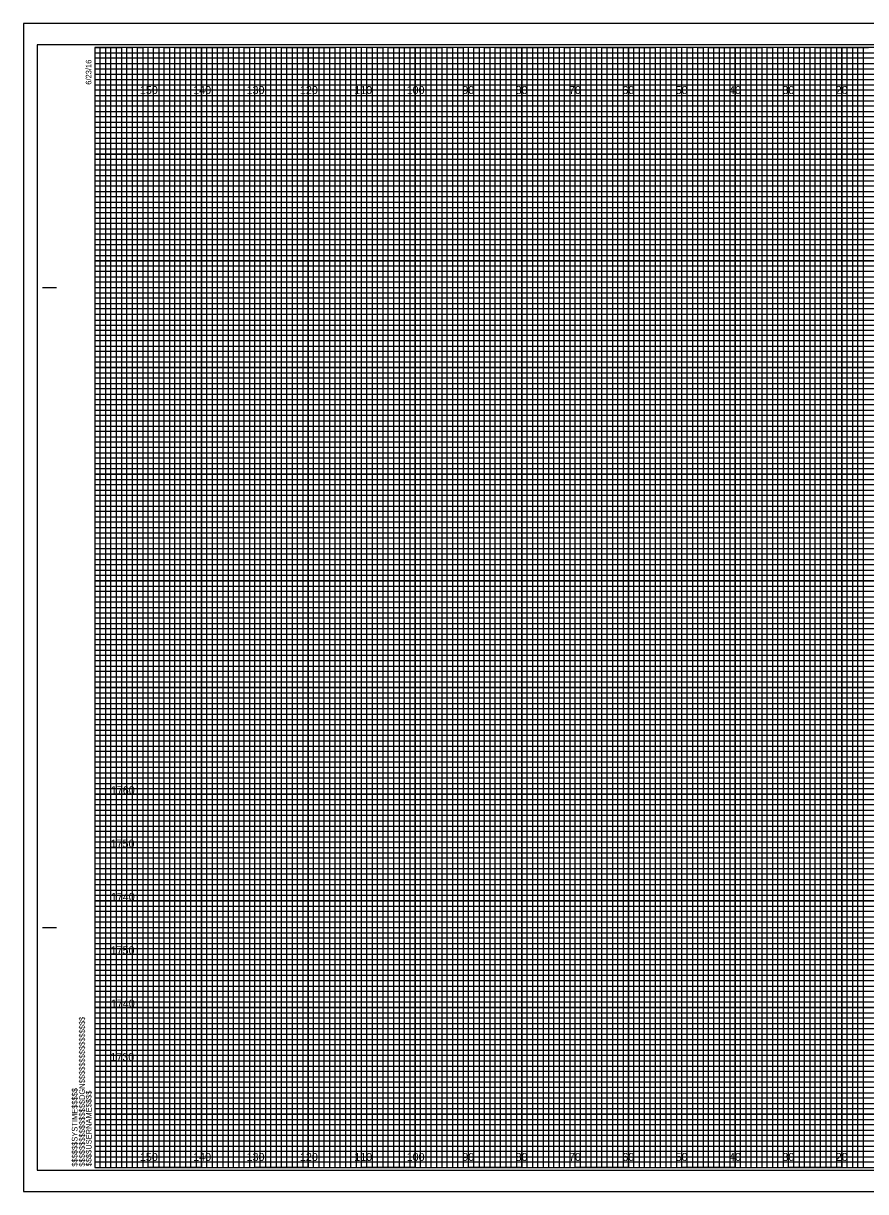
# Model space of a CAD drawing. Extents: x -13 to 323, y -5 to 434.
# Drawn here: x -13.4 to 144.5, y 215.5 to 434.5 of the extents above; entities that cross this region are included whole.
import ezdxf

# ---------------------------------------------------------------- set-up
doc = ezdxf.new("R2010")
doc.units = 0
for name, color, linetype in [('Raster_Level_0', 7, 'Continuous'), ('Scratch_Level_3', 7, 'Continuous'), ('Sheet Cross Section CELL', 7, 'Continuous'), ('Sheet Cross Section Grid Major CELL', 7, 'Continuous'), ('Sheet Cross Section Grid Middle CELL', 7, 'Continuous'), ('Sheet Cross Section Grid Minor 1 CELL', 7, 'Continuous'), ('Sheet Cross Section Grid Minor 2 CELL', 7, 'Continuous'), ('Sheet Cutting Line CELL', 7, 'Continuous'), ('Sheet DOT Grid CELL', 7, 'Continuous'), ('Sheet Plot Border Inside CELL', 7, 'Continuous'), ('Sheet Plot Border Outside CELL', 7, 'Continuous')]:
    doc.layers.add(name, color=color, linetype=linetype)

msp = doc.modelspace()

# ---------------------------------------------------------------- linework, layer by layer
at = {"layer": 'Sheet Cross Section CELL'}
for p, q in [((-9.8, 385), (-7.3, 385)), ((-9.7, 385), (-7.2, 385)), ((-9.8, 265), (-7.3, 265)), ((-9.7, 265), (-7.2, 265)), ((0, 220), (0, 220)), ((0, 220), (0, 220)), ((0, 220), (0, 220)), ((0, 220), (0, 220)), ((0, 220), (0, 220)), ((0, 220), (0, 220)), ((0, 220), (0, 220))]:
    msp.add_line(p, q, dxfattribs=at)
msp.add_lwpolyline([(320, 430), (0, 430), (0, 220), (320, 220)], close=True, dxfattribs=at)
at = {"layer": 'Sheet Cross Section Grid Major CELL'}
for p, q in [((10, 430), (0, 430)), ((10, 220), (10, 430)), ((30, 430), (20, 430)), ((20, 430), (20, 220)), ((30, 220), (30, 430)), ((50, 430), (40, 430)), ((40, 430), (40, 220)), ((50, 220), (50, 430)), ((70, 430), (60, 430)), ((60, 430), (60, 220)), ((70, 220), (70, 430)), ((90, 430), (80, 430)), ((80, 430), (80, 220)), ((90, 220), (90, 430)), ((110, 430), (100, 430)), ((100, 430), (100, 220)), ((110, 220), (110, 430)), ((130, 430), (120, 430)), ((120, 430), (120, 220)), ((130, 220), (130, 430)), ((150, 430), (140, 430)), ((140, 430), (140, 220)), ((20, 220), (10, 220)), ((40, 220), (30, 220)), ((60, 220), (50, 220)), ((80, 220), (70, 220)), ((100, 220), (90, 220)), ((120, 220), (110, 220)), ((140, 220), (130, 220))]:
    msp.add_line(p, q, dxfattribs=at)
for points in [[(0, 420), (320, 420), (320, 410), (0, 410)], [(0, 400), (320, 400), (320, 390), (0, 390)], [(0, 380), (320, 380), (320, 370), (0, 370)], [(0, 360), (320, 360), (320, 350), (0, 350)], [(0, 340), (320, 340), (320, 330), (0, 330)], [(0, 320), (320, 320), (320, 310), (0, 310)], [(0, 300), (320, 300), (320, 290), (0, 290)], [(0, 280), (320, 280), (320, 270), (0, 270)], [(0, 260), (320, 260), (320, 250), (0, 250)], [(0, 240), (320, 240), (320, 230), (0, 230)]]:
    msp.add_lwpolyline(points, dxfattribs=at)
at = {"layer": 'Sheet Cross Section Grid Middle CELL'}
for points in [[(0, 430), (5, 430), (5, 220), (15, 220), (15, 430), (25, 430), (25, 220), (35, 220), (35, 430), (45, 430), (45, 220), (55, 220), (55, 430), (65, 430), (65, 220), (75, 220), (75, 430), (85, 430), (85, 220), (95, 220), (95, 430), (105, 430), (105, 220), (115, 220), (115, 430), (125, 430), (125, 220), (135, 220), (135, 430), (145, 430)], [(0, 425), (275, 425)], [(0, 405), (320, 405), (320, 415), (0, 415)], [(0, 385), (320, 385), (320, 395), (0, 395)], [(0, 365), (320, 365), (320, 375), (0, 375)], [(0, 345), (320, 345), (320, 355), (0, 355)], [(0, 325), (320, 325), (320, 335), (0, 335)], [(0, 305), (320, 305), (320, 315), (0, 315)], [(0, 285), (320, 285), (320, 295), (0, 295)], [(0, 265), (320, 265), (320, 275), (0, 275)], [(0, 245), (320, 245), (320, 255), (0, 255)], [(0, 225), (320, 225), (320, 235), (0, 235)]]:
    msp.add_lwpolyline(points, dxfattribs=at)
at = {"layer": 'Sheet Cross Section Grid Minor 1 CELL'}
for p, q in [((0, 429), (260, 429)), ((260, 427.98), (0, 427.98)), ((0, 427.98), (0, 427)), ((0, 427), (260, 427)), ((260, 425.89), (0, 425.89)), ((0, 425.89), (0, 424)), ((0, 424), (320, 424))]:
    msp.add_line(p, q, dxfattribs=at)
for points in [[(0, 423), (270, 423), (320, 423), (320, 422), (0, 422)], [(0, 421), (320, 421), (320, 419), (0, 419)], [(0, 418), (320, 418), (320, 417), (0, 416.98)], [(0, 416), (320, 416), (320, 414), (0, 414)], [(0, 413), (320, 413), (320, 412), (0, 412)], [(0, 411), (320, 411), (320, 409), (0, 409)], [(0, 408), (320, 408), (320, 407), (0, 407)], [(0, 406), (320, 406), (320, 404), (0, 404)], [(0, 403), (320, 403), (320, 402), (0, 402)], [(0, 401), (320, 401), (320, 399), (0, 399)], [(0, 398), (320, 398), (320, 397), (0, 397)], [(0, 396), (320, 396), (320, 393.95), (320, 393), (320, 392), (0, 392)], [(0, 394), (320, 394), (320, 393), (0, 393)], [(0, 391), (320, 391), (320, 389), (0, 389.03)], [(0, 389.03), (320, 389), (320, 388), (0, 388)], [(0, 387), (320, 387), (320, 386), (0, 386)], [(0, 384), (320, 384), (320, 383), (0, 383)], [(0, 382), (320, 382), (320, 381), (0, 381)], [(-0.07, 378.89), (320, 378.89), (320, 377.88), (-0.07, 377.88)], [(0, 377), (320, 377), (320, 376), (0, 376)], [(0, 374), (320, 374), (320, 373), (0, 373)], [(0, 372), (320, 372), (320, 371), (0, 371)], [(0, 369), (320, 369), (320, 368), (0, 368)], [(0, 367), (320, 367), (320, 366), (0, 366)], [(0, 364), (320, 364), (320, 363), (0, 363)], [(0, 362), (320, 362), (320, 361), (0, 361)], [(0, 359), (320, 359), (319.99, 357.98), (0, 358)], [(0, 357), (320, 357), (320, 356), (0, 356)], [(0, 354), (320, 354), (320, 353), (0, 353)], [(0, 352), (320, 352), (320, 351), (0, 351)], [(0, 349), (320, 349), (320, 348), (0, 348)], [(0, 347), (320, 347), (320, 346), (0, 346)], [(0, 344), (320, 344), (320, 343), (0, 343)], [(0, 342), (320, 342), (320, 341), (0, 341)], [(0, 339), (320, 339), (320, 338), (0, 338)], [(0, 336.99), (320.07, 336.91), (320, 336), (0, 336)], [(0, 334), (320, 334), (320, 333), (0, 333)], [(0, 332), (320, 332), (320, 331), (0, 331)], [(0, 329), (320, 329), (320, 328), (0, 328)], [(0, 327), (320, 327), (320, 326), (0, 326)], [(0, 324), (320, 324), (320, 323), (0, 323)], [(0, 322), (320, 322), (320, 321), (0, 321)], [(0, 319), (320, 319), (320, 318), (0, 318)], [(0, 317), (320, 317), (320, 316), (0, 316)], [(0, 314), (320, 314), (320, 313), (0, 313)], [(0, 312), (320, 312), (320, 311), (0, 311)], [(0, 309), (320, 309), (320, 308), (0, 308)], [(0, 307), (320, 307), (320, 306), (0, 306)], [(0, 304), (320, 304), (320, 303), (0, 303)], [(0, 302), (320, 302), (320, 301), (0, 301)], [(0, 299), (320, 299), (319.99, 297.98), (0, 298)], [(0, 297), (320, 297), (320, 296), (0, 296)], [(0, 294), (320, 294), (320, 293), (0, 293)], [(0, 292), (320, 292), (320, 291), (0, 291)], [(0, 289), (320, 289), (320, 288), (0, 288)], [(0, 287), (320, 287), (320, 286), (0, 286)], [(0, 284), (320, 284), (320, 283), (0, 283)], [(0, 282), (320, 282), (320, 281), (0, 281)], [(0, 279), (320, 279), (320, 278), (0, 278)], [(0, 276.99), (320.07, 276.91), (320, 276), (0, 276)], [(0, 274), (320, 274), (320, 273), (0, 273)], [(0, 272), (320, 272), (320, 271), (0, 271)], [(0, 269), (320, 269), (320, 268), (0, 268)], [(0, 267), (320, 267), (320, 266), (0, 266)], [(0, 264), (320, 264), (320, 263), (0, 263)], [(0, 262), (320, 262), (320, 261), (0, 261)], [(0, 259), (320, 259), (320, 258), (0, 258)], [(0, 257), (320, 257), (320, 256), (0, 256)], [(0, 254), (320, 254), (320, 253), (0, 253)], [(0, 252), (320, 252), (320, 251), (0, 251)], [(0, 249), (320, 249), (320, 248), (0, 248)], [(0, 247), (320, 247), (320, 246), (0, 246)], [(0, 244), (320, 244), (320, 243), (0, 243)], [(0, 242), (320, 242), (320, 241), (0, 241)], [(0, 239), (320, 239), (320, 238), (0, 238)], [(0, 237), (320, 237), (320, 236), (0, 236)], [(0, 234), (320, 234), (320, 233), (0, 233)], [(0, 232), (320, 232), (320, 231), (0, 231)], [(0, 229), (320, 229), (320, 228), (0, 228)], [(0, 227), (320, 227), (320, 226), (0, 226)], [(0, 224), (320, 224), (320, 223), (0, 223)], [(0, 222), (320, 222), (320, 221), (0, 221)]]:
    msp.add_lwpolyline(points, dxfattribs=at)
at = {"layer": 'Sheet Cross Section Grid Minor 2 CELL'}
for points in [[(0, 220), (1, 220), (1, 430), (2, 430), (2, 220)], [(2, 220), (3, 220), (3, 430), (4, 430), (4, 220)], [(5, 220), (6, 220), (6, 430), (7, 430), (7, 220)], [(7, 220), (8, 220), (8, 430), (9, 430), (9, 220)], [(10, 220), (11, 220), (11, 430), (12, 430), (12, 220)], [(12, 220), (13, 220), (13, 430), (14, 430), (14, 220)], [(15, 220), (16, 220), (16, 430), (17, 430), (17, 220)], [(17, 220), (18, 220), (18, 430), (19, 430), (19, 220)], [(20, 220), (21, 220), (21, 430), (22, 430), (22, 220)], [(22, 220), (23, 220), (23, 430), (24, 430), (24, 220)], [(25, 220), (26, 220), (26, 430), (27, 430), (27, 220)], [(27, 220), (28, 220), (28, 430), (29, 430), (29, 220)], [(30, 220), (31, 220), (31, 430), (32, 430), (32, 220)], [(32, 220), (33, 220), (33, 430), (34, 430), (34, 220)], [(35, 220), (36, 220), (36, 430), (37, 430), (37, 220)], [(37, 220), (38, 220), (38, 430), (39, 430), (39, 220)], [(40, 220), (41, 220), (41, 430), (42, 430), (42, 220)], [(42, 220), (43, 220), (43, 430), (44, 430), (44, 220)], [(45, 220), (46, 220), (46, 430), (47, 430), (47, 220)], [(47, 220), (48, 220), (48, 430), (49, 430), (49, 220)], [(50, 220), (51, 220), (51, 430), (52, 430), (52, 220)], [(52, 220), (53, 220), (53, 430), (54, 430), (54, 220)], [(55, 220), (56, 220), (56, 430), (57, 430), (57, 220)], [(57, 220), (58, 220), (58, 430), (59, 430), (59, 220)], [(60, 220), (61, 220), (61, 430), (62, 430), (62, 220)], [(62, 220), (63, 220), (63, 430), (64, 430), (64, 220)], [(65, 220), (66, 220), (66, 430), (67, 430), (67, 220)], [(67, 220), (68, 220), (68, 430), (69, 430), (69, 220)], [(70, 220), (71, 220), (71, 430), (72, 430), (72, 220)], [(72, 220), (73, 220), (73, 430), (74, 430), (74, 220)], [(75, 220), (76, 220), (76, 430), (77, 430), (77, 220)], [(77, 220), (78, 220), (78, 430), (79, 430), (79, 220)], [(80, 220), (81, 220), (81, 430), (82, 430), (82, 220)], [(82, 220), (83, 220), (83, 430), (84, 430), (84, 220)], [(85, 220), (86, 220), (86, 430), (87, 430), (87, 220)], [(87, 220), (88, 220), (88, 430), (89, 430), (89, 220)], [(90, 220), (91, 220), (91, 430), (92, 430), (92, 220)], [(92, 220), (93, 220), (93, 430), (94, 430), (94, 220)], [(95, 220), (96, 220), (96, 430), (97, 430), (97, 220)], [(97, 220), (98, 220), (98, 430), (99, 430), (99, 220)], [(100, 220), (101, 220), (101, 430), (102, 430), (102, 220)], [(102, 220), (103, 220), (103, 430), (104, 430), (104, 220)], [(105, 220), (106, 220), (106, 430), (107, 430), (107, 220)], [(107, 220), (108, 220), (108, 430), (109, 430), (109, 220)], [(110, 220), (111, 220), (111, 430), (112, 430), (112, 220)], [(112, 220), (113, 220), (113, 430), (114, 430), (114, 220)], [(115, 220), (116, 220), (116, 430), (117, 430), (117, 220)], [(117, 220), (118, 220), (118, 430), (119, 430), (119, 220)], [(120, 220), (121, 220), (121, 430), (122, 430), (122, 220)], [(122, 220), (123, 220), (123, 430), (124, 430), (124, 220)], [(125, 220), (126, 220), (126, 430), (127, 430), (127, 220)], [(127, 220), (128, 220), (128, 430), (129, 430), (129, 220)], [(130, 220), (131, 220), (131, 430), (132, 430), (132, 220)], [(132, 220), (133, 220), (133, 430), (134, 430), (134, 220)], [(135, 220), (136, 220), (136, 430), (137, 430), (137, 220)], [(137, 220), (138, 220), (138, 430), (139, 430), (139, 220)], [(140, 220), (141, 220), (141, 430), (142, 430), (142, 220)], [(142, 220), (143, 220), (143, 430), (144, 430), (144, 220)]]:
    msp.add_lwpolyline(points, dxfattribs=at)
at = {"layer": 'Sheet Cutting Line CELL'}
for p, q in [((323.3, 434.5), (-13.4, 434.5)), ((-13.4, 434.5), (-13.4, 215.5)), ((-13.4, 215.5), (323.3, 215.5))]:
    msp.add_line(p, q, dxfattribs=at)
at = {"layer": 'Sheet DOT Grid CELL'}
for p, q in [((10, 220), (10, 430)), ((20, 220), (20, 430)), ((30, 220), (30, 430)), ((40, 220), (40, 430)), ((50, 220), (50, 430)), ((60, 220), (60, 430)), ((70, 220), (70, 430)), ((80, 220), (80, 430)), ((90, 220), (90, 430)), ((100, 220), (100, 430)), ((110, 220), (110, 430)), ((120, 220), (120, 430)), ((130, 220), (130, 430)), ((140, 220), (140, 430)), ((0, 420), (320, 420)), ((0, 410), (320, 410)), ((0, 400), (320, 400)), ((0, 390), (320, 390)), ((0, 380), (320, 380)), ((0, 370), (320, 370)), ((0, 360), (320, 360)), ((0, 350), (320, 350)), ((0, 340), (320, 340)), ((0, 330), (320, 330)), ((0, 320), (320, 320)), ((0, 310), (320, 310)), ((0, 300), (320, 300)), ((0, 290), (320, 290)), ((0, 280), (320, 280)), ((0, 270), (320, 270)), ((0, 260), (320, 260)), ((0, 250), (320, 250)), ((0, 240), (320, 240)), ((0, 230), (320, 230))]:
    msp.add_line(p, q, dxfattribs=at)
at = {"layer": 'Sheet Plot Border Inside CELL'}
msp.add_lwpolyline([(-10.8, 219.5), (322.4, 219.5), (322.4, 430.5), (-10.8, 430.5)], close=True, dxfattribs=at)
at = {"layer": 'Sheet Plot Border Outside CELL'}
msp.add_lwpolyline([(-13.4, 215.5), (323.3, 215.5), (323.3, 434.5), (-13.4, 434.5)], close=True, dxfattribs=at)

# ---------------------------------------------------------------- texts
at = {"layer": 'Raster_Level_0'}
for s, p in [('150', (8.44, 421.25)), ('140', (18.44, 421.25)), ('130', (28.44, 421.25)), ('120', (38.44, 421.25)), ('110', (48.62, 421.25)), ('100', (58.44, 421.25)), ('90', (68.86, 421.25)), ('80', (78.86, 421.25)), ('70', (88.86, 421.25)), ('60', (98.86, 421.25)), ('50', (108.86, 421.25)), ('40', (118.86, 421.25)), ('30', (128.86, 421.25)), ('20', (138.86, 421.25)), ('150', (8.44, 221.25)), ('140', (18.44, 221.25)), ('130', (28.44, 221.25)), ('120', (38.44, 221.25)), ('110', (48.62, 221.25)), ('100', (58.44, 221.25)), ('90', (68.86, 221.25)), ('80', (78.86, 221.25)), ('70', (88.86, 221.25)), ('60', (98.86, 221.25)), ('50', (108.86, 221.25)), ('40', (118.86, 221.25)), ('30', (128.86, 221.25)), ('20', (138.86, 221.25))]:
    msp.add_text(s, height=1.5, dxfattribs=at).set_placement(p)
at = {"layer": 'Scratch_Level_3'}
for s, p in [('1760', (3, 290)), ('1750', (2.96, 280)), ('1740', (3, 270)), ('1750', (2.96, 260)), ('1740', (3, 250)), ('1730', (2.92, 240))]:
    msp.add_text(s, height=1.5, dxfattribs=at).set_placement(p)
at = {"layer": 'Sheet Cross Section CELL'}
for s, p in [('6/23/16', (-0.65, 423)), ('$$$$$$$$$$$$$$$$DGN$$$$$$$$$$$$$$$$', (-1.88, 220.18)), ('$$$$$$SYSTIME$$$$$', (-3.26, 220.18)), ('$$$$USERNAME$$$$', (-0.62, 220.23))]:
    msp.add_text(s, height=1.05, rotation=90, dxfattribs=at).set_placement(p)

doc.saveas('drawing.dxf')
